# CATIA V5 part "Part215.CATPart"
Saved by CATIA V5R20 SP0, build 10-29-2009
Part number: IA 1007SF
Revision: ANY
Definition: UNKNOWN
Nomenclature: IA 1007SF
Source: Unknown
Bounding box of the stored display mesh (mm): x -5.35 to 5.35, y -17 to 0, z -5.35 to 5.35
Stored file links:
  C:\Users\Utente\Desktop\IO LAVORO\3D X SITO CF\CUMSA\3D files FA\FA 200710-20\Part215.CATPart

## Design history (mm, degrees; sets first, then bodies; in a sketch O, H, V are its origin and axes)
Body1 "Cortar-Extruir1" (main body)
  Solid1: solid without history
